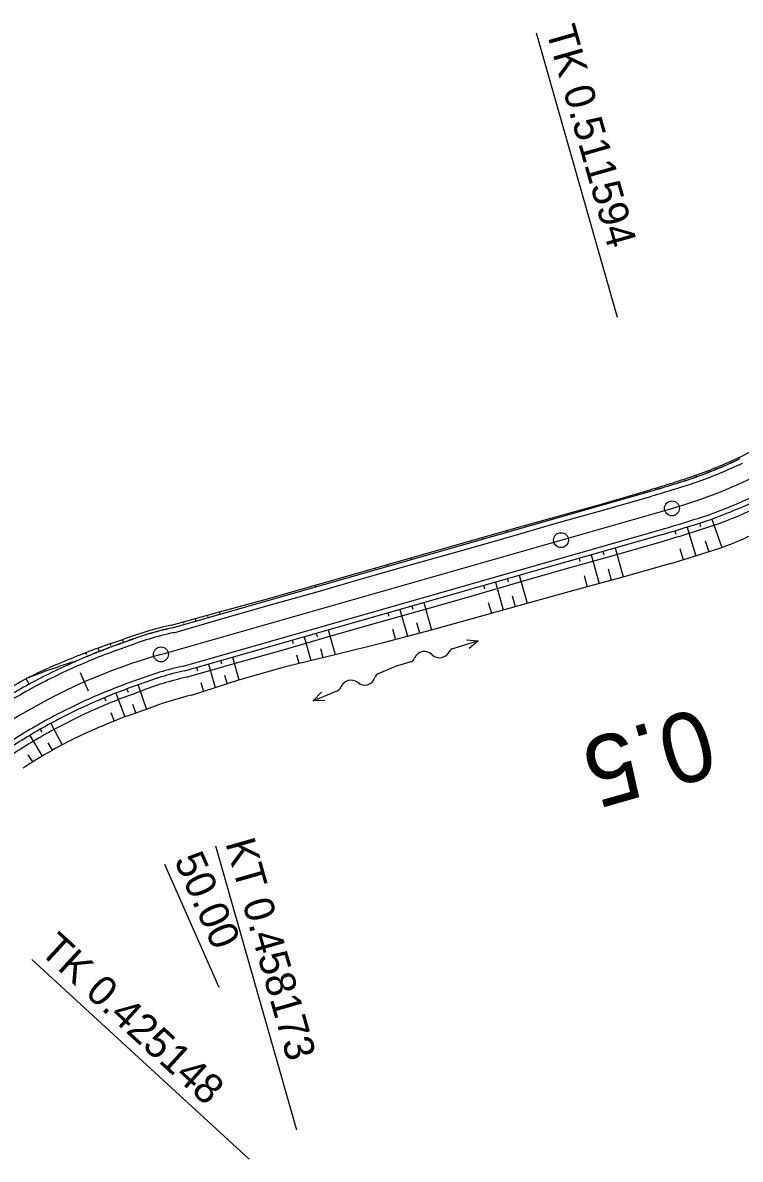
# Model space of a CAD drawing. Extents: x -481645 to -478728, y -1113199 to -1110710.
# Drawn here: x -479608.4 to -479536.3, y -1111488.4 to -1111374.2 of the extents above; entities that cross this region are included whole.
import ezdxf

# ---------------------------------------------------------------- set-up
doc = ezdxf.new("R2010")
doc.units = 0
for name, color, linetype in [('CP14_HATCH_SLOPE_L', 7, 'Continuous'), ('CP14_HECTOMETRY', 7, 'Continuous'), ('CP14_HLBODY', 7, 'Continuous'), ('CP1_HECTOMETRY', 7, 'Continuous'), ('O6_HATCH_SLOPE_L', 7, 'Continuous'), ('O6_HATCH_SLOPE_R', 7, 'Continuous'), ('O6_HECTOMETRY', 7, 'Continuous'), ('O6_HLBODY', 7, 'Continuous'), ('O6_HRANA_TELESO', 7, 'Continuous'), ('O6_OSA', 7, 'Continuous'), ('O6_VOZOVKA', 7, 'Continuous'), ('O6_ZPEVKRAJ', 7, 'Continuous')]:
    doc.layers.add(name, color=color, linetype=linetype)

# ---------------------------------------------------------------- blocks, each defined once
blk = doc.blocks.new('A$C70B')
at = {"layer": 'CP14_HLBODY'}
for p, q in [((0.87, 0), (-0.87, 0)), ((6.86, 0.43), (7.97, 0)), ((7.97, 0), (5.28, 0)), ((7.97, 0), (6.86, -0.48))]:
    blk.add_line(p, q, dxfattribs=at)
for centre, radius, start, end in [((0.87, 0.58), 0.582, 269.6924, 322.7901), ((2.17, -0.42), 1.05, 24.4039, 142.0836), ((4.08, 0.59), 1.11, 210.8873, 317.3707), ((5.32, -0.64), 0.636, 85.9766, 131.7248)]:
    blk.add_arc(centre, radius, start, end, dxfattribs=at)

msp = doc.modelspace()

# ---------------------------------------------------------------- linework, layer by layer
at = {"layer": 'CP14_HATCH_SLOPE_L'}
for p, q in [((-479539.17, -1111424.02), (-479538.14, -1111426.88)), ((-479542.88, -1111425.21), (-479542.79, -1111425.53)), ((-479541.64, -1111424.85), (-479540.76, -1111427.75)), ((-479540.4, -1111424.45), (-479540.29, -1111424.77)), ((-479539.82, -1111426.21), (-479539.44, -1111427.33)), ((-479551.3, -1111427.61), (-479550.48, -1111430.49)), ((-479550.1, -1111427.27), (-479550, -1111427.59)), ((-479548.89, -1111426.93), (-479548.07, -1111429.83)), ((-479542.38, -1111426.99), (-479542.05, -1111428.13)), ((-479552.5, -1111427.96), (-479552.41, -1111428.28)), ((-479559.71, -1111430.02), (-479559.62, -1111430.34)), ((-479558.51, -1111429.67), (-479557.71, -1111432.47)), ((-479552, -1111429.71), (-479551.68, -1111430.82)), ((-479549.59, -1111429.03), (-479549.27, -1111430.16)), ((-479562.11, -1111430.7), (-479562.02, -1111431.02)), ((-479560.91, -1111430.36), (-479560.12, -1111433.14)), ((-479568.12, -1111432.42), (-479567.35, -1111435.14)), ((-479561.63, -1111432.41), (-479561.32, -1111433.47)), ((-479559.22, -1111431.73), (-479558.92, -1111432.8)), ((-479571.73, -1111433.45), (-479571.64, -1111433.77)), ((-479570.53, -1111433.1), (-479569.76, -1111435.79)), ((-479569.33, -1111432.76), (-479569.23, -1111433.08)), ((-479568.85, -1111434.43), (-479568.55, -1111435.47)), ((-479580.14, -1111435.85), (-479579.47, -1111438.22)), ((-479578.94, -1111435.51), (-479578.85, -1111435.83)), ((-479577.74, -1111435.16), (-479577.04, -1111437.63)), ((-479571.26, -1111435.1), (-479570.97, -1111436.12)), ((-479581.35, -1111436.19), (-479581.25, -1111436.51)), ((-479587.36, -1111437.91), (-479586.71, -1111440.18)), ((-479580.92, -1111437.67), (-479580.68, -1111438.51)), ((-479578.51, -1111437.03), (-479578.25, -1111437.92)), ((-479590.96, -1111438.94), (-479590.87, -1111439.26)), ((-479589.76, -1111438.59), (-479589.09, -1111440.96)), ((-479588.56, -1111438.25), (-479588.47, -1111438.56)), ((-479588.14, -1111439.72), (-479587.9, -1111440.57)), ((-479599.09, -1111441.53), (-479598.16, -1111443.91)), ((-479597.97, -1111441.1), (-479597.85, -1111441.42)), ((-479596.83, -1111440.7), (-479595.99, -1111443.15)), ((-479590.53, -1111440.46), (-479590.28, -1111441.35)), ((-479600.21, -1111441.98), (-479600.08, -1111442.29)), ((-479597.41, -1111442.63), (-479597.08, -1111443.52)), ((-479599.59, -1111443.47), (-479599.24, -1111444.32)), ((-479605.63, -1111444.57), (-479604.48, -1111446.7)), ((-479607.72, -1111445.76), (-479606.48, -1111447.84)), ((-479606.69, -1111445.15), (-479606.52, -1111445.45)), ((-479605.91, -1111446.51), (-479605.48, -1111447.26)), ((-479607.93, -1111447.7), (-479607.47, -1111448.43))]:
    msp.add_line(p, q, dxfattribs=at)
at = {"layer": 'CP1_HECTOMETRY'}
msp.add_line((-479594.54, -1111437.62), (-479543.17, -1111422.95), dxfattribs=at)
for centre, radius, start, end in [((-479556.9, -1111374.87), 50, 285.9337, 309.1802), ((-479578.07, -1111495.31), 60, 105.9337, 137.4702)]:
    msp.add_arc(centre, radius, start, end, dxfattribs=at)
at = {"layer": 'O6_HATCH_SLOPE_L'}
msp.add_circle((-479554.32, -1111426.14), 0.75, dxfattribs=at)
at = {"layer": 'O6_HATCH_SLOPE_R'}
for p, q in [((-479540.69, -1111419.79), (-479540.76, -1111419.62)), ((-479542.96, -1111420.54), (-479543.01, -1111420.38)), ((-479541.85, -1111420.09), (-479541.88, -1111420.02)), ((-479541.82, -1111420.18), (-479541.82, -1111420.18)), ((-479552.53, -1111423.29), (-479552.57, -1111423.16)), ((-479551.35, -1111422.88), (-479551.36, -1111422.82)), ((-479551.33, -1111422.94), (-479551.33, -1111422.94)), ((-479550.13, -1111422.6), (-479550.16, -1111422.49)), ((-479553.76, -1111423.56), (-479553.77, -1111423.49)), ((-479553.73, -1111423.63), (-479553.74, -1111423.62)), ((-479560.97, -1111425.6), (-479561, -1111425.51)), ((-479559.74, -1111425.34), (-479559.79, -1111425.17)), ((-479563.38, -1111426.28), (-479563.4, -1111426.2)), ((-479563.35, -1111426.38), (-479563.35, -1111426.37)), ((-479562.15, -1111426.03), (-479562.2, -1111425.86)), ((-479560.95, -1111425.69), (-479560.95, -1111425.68)), ((-479572.99, -1111429.03), (-479573.01, -1111428.95)), ((-479571.76, -1111428.78), (-479571.81, -1111428.61)), ((-479570.59, -1111428.34), (-479570.61, -1111428.27)), ((-479570.56, -1111428.43), (-479570.56, -1111428.43)), ((-479569.36, -1111428.09), (-479569.41, -1111427.92)), ((-479572.97, -1111429.12), (-479572.97, -1111429.12)), ((-479580.2, -1111431.08), (-479580.23, -1111431)), ((-479580.18, -1111431.18), (-479580.18, -1111431.17)), ((-479578.98, -1111430.84), (-479579.03, -1111430.66)), ((-479588.59, -1111433.58), (-479588.66, -1111433.35)), ((-479592.24, -1111434.48), (-479592.27, -1111434.35)), ((-479592.2, -1111434.61), (-479592.2, -1111434.61)), ((-479590.99, -1111434.27), (-479591.07, -1111434.02)), ((-479589.83, -1111433.8), (-479589.86, -1111433.69)), ((-479589.79, -1111433.92), (-479589.79, -1111433.92)), ((-479600.73, -1111437.34), (-479600.86, -1111437)), ((-479599.58, -1111436.72), (-479599.63, -1111436.56)), ((-479599.52, -1111436.88), (-479599.52, -1111436.87)), ((-479598.3, -1111436.44), (-479598.39, -1111436.16)), ((-479602.01, -1111437.63), (-479602.09, -1111437.45)), ((-479601.93, -1111437.82), (-479601.94, -1111437.82)), ((-479607.78, -1111440.61), (-479608.09, -1111440.06))]:
    msp.add_line(p, q, dxfattribs=at)
at = {"layer": 'O6_HECTOMETRY'}
for p, q in [((-479556.81, -1111375.16), (-479548.66, -1111403.72)), ((-479589.05, -1111456.85), (-479580.9, -1111485.41)), ((-479607.54, -1111468.27), (-479585.66, -1111488.35))]:
    msp.add_line(p, q, dxfattribs=at)
for centre in [(-479543.17, -1111422.95), (-479594.54, -1111437.62), (-479594.54, -1111437.62)]:
    msp.add_circle(centre, 0.75, dxfattribs=at)
at = {"layer": 'O6_HLBODY'}
for p, q in [((-479601.82, -1111441.3), (-479602.62, -1111439.48)), ((-479601.82, -1111441.3), (-479602.62, -1111439.48)), ((-479594.17, -1111458.7), (-479588.73, -1111471.06))]:
    msp.add_line(p, q, dxfattribs=at)
at = {"layer": 'O6_HRANA_TELESO'}
for p, q in [((-479550.13, -1111422.59), (-479545.32, -1111421.22)), ((-479554.94, -1111423.96), (-479550.13, -1111422.59)), ((-479559.75, -1111425.34), (-479554.94, -1111423.96)), ((-479564.55, -1111426.71), (-479559.75, -1111425.34)), ((-479569.36, -1111428.08), (-479564.55, -1111426.71)), ((-479548.71, -1111427.57), (-479543.9, -1111426.2)), ((-479553.52, -1111428.94), (-479548.71, -1111427.57)), ((-479574.17, -1111429.45), (-479569.36, -1111428.08)), ((-479558.33, -1111430.31), (-479553.52, -1111428.94)), ((-479578.98, -1111430.83), (-479574.17, -1111429.45)), ((-479583.79, -1111432.2), (-479578.98, -1111430.83)), ((-479563.13, -1111431.69), (-479558.33, -1111430.31)), ((-479588.59, -1111433.57), (-479583.79, -1111432.2)), ((-479567.94, -1111433.06), (-479563.13, -1111431.69)), ((-479593.4, -1111434.94), (-479588.59, -1111433.57)), ((-479572.75, -1111434.43), (-479567.94, -1111433.06)), ((-479577.56, -1111435.8), (-479572.75, -1111434.43)), ((-479582.36, -1111437.18), (-479577.56, -1111435.8)), ((-479587.18, -1111438.53), (-479582.36, -1111437.18)), ((-479591.98, -1111439.92), (-479587.18, -1111438.53))]:
    msp.add_line(p, q, dxfattribs=at)
for centre, radius, start, end in [((-479556.9, -1111374.87), 47.74, 289.8361, 295.5657), ((-479585.46, -1111283.74), 143.22, 286.2737, 288.212), ((-479556.9, -1111374.87), 52.92, 289.8361, 295.5657), ((-479588.59, -1111273.86), 158.75, 286.3485, 288.2244), ((-479586.83, -1111465.37), 31.13, 102.1921, 111.6239), ((-479578.07, -1111495.31), 62.26, 108.9637, 113.7383), ((-479584.95, -1111498.19), 62.57, 106.893, 111.7018), ((-479585.96, -1111467.81), 28.53, 102.1841, 111.9235), ((-479577.99, -1111495.28), 57.06, 109.0427, 113.8173), ((-479578.07, -1111495.32), 57.06, 113.7302, 118.5049), ((-479578.08, -1111495.32), 57.06, 118.4928, 123.2674)]:
    msp.add_arc(centre, radius, start, end, dxfattribs=at)
at = {"layer": 'O6_OSA'}
for p, q in [((-479550.16, -1111422.49), (-479545.36, -1111421.08)), ((-479554.98, -1111423.83), (-479550.16, -1111422.49)), ((-479559.79, -1111425.17), (-479554.98, -1111423.83)), ((-479564.6, -1111426.55), (-479559.79, -1111425.17)), ((-479569.41, -1111427.92), (-479564.6, -1111426.55)), ((-479574.22, -1111429.29), (-479569.41, -1111427.92)), ((-479548.07, -1111429.83), (-479543.25, -1111428.47)), ((-479579.03, -1111430.66), (-479574.22, -1111429.29)), ((-479552.89, -1111431.15), (-479548.07, -1111429.83)), ((-479583.84, -1111432.03), (-479579.03, -1111430.66)), ((-479557.71, -1111432.47), (-479552.89, -1111431.15)), ((-479588.66, -1111433.35), (-479583.84, -1111432.03)), ((-479593.48, -1111434.69), (-479588.66, -1111433.35)), ((-479562.53, -1111433.8), (-479557.71, -1111432.47)), ((-479567.35, -1111435.14), (-479562.53, -1111433.8)), ((-479572.17, -1111436.44), (-479567.35, -1111435.14)), ((-479577.04, -1111437.63), (-479572.17, -1111436.44)), ((-479581.9, -1111438.81), (-479577.04, -1111437.63)), ((-479586.71, -1111440.18), (-479581.9, -1111438.81)), ((-479591.46, -1111441.73), (-479586.71, -1111440.18))]:
    msp.add_line(p, q, dxfattribs=at)
for centre, radius, start, end in [((-479557.01, -1111374.94), 47.59, 295.727, 301.4566), ((-479556.63, -1111374.76), 47.58, 289.4838, 295.2135), ((-479586.33, -1111284.4), 142.69, 286.6836, 288.6246), ((-479557.96, -1111375.33), 55.23, 291.0412, 296.7721), ((-479590.04, -1111269.36), 165.85, 286.3861, 288.2374), ((-479587.01, -1111465.29), 31.28, 101.9322, 111.3477), ((-479579.52, -1111495.86), 62.62, 107.5444, 112.3205), ((-479580.3, -1111496.35), 62.78, 111.4945, 116.2728), ((-479577.83, -1111495.17), 62.87, 118.7699, 123.5446), ((-479585.5, -1111468.66), 27.58, 102.4827, 112.3513), ((-479578.96, -1111495.65), 55.19, 107.9753, 112.7506), ((-479579.04, -1111495.78), 55.28, 112.6168, 117.3924), ((-479578.25, -1111495.43), 55.33, 118.2878, 123.0624)]:
    msp.add_arc(centre, radius, start, end, dxfattribs=at)
at = {"layer": 'O6_VOZOVKA'}
for p, q in [((-479549.99, -1111423.08), (-479545.18, -1111421.71)), ((-479554.8, -1111424.45), (-479549.99, -1111423.08)), ((-479559.61, -1111425.83), (-479554.8, -1111424.45)), ((-479549.03, -1111426.45), (-479544.22, -1111425.07)), ((-479564.42, -1111427.2), (-479559.61, -1111425.83)), ((-479553.84, -1111427.82), (-479549.03, -1111426.45)), ((-479569.22, -1111428.57), (-479564.42, -1111427.2)), ((-479558.65, -1111429.19), (-479553.84, -1111427.82)), ((-479574.03, -1111429.94), (-479569.22, -1111428.57)), ((-479578.84, -1111431.32), (-479574.03, -1111429.94)), ((-479563.45, -1111430.56), (-479558.65, -1111429.19)), ((-479568.26, -1111431.94), (-479563.45, -1111430.56)), ((-479583.65, -1111432.69), (-479578.84, -1111431.32)), ((-479573.07, -1111433.31), (-479568.26, -1111431.94)), ((-479588.45, -1111434.06), (-479583.65, -1111432.69)), ((-479577.88, -1111434.68), (-479573.07, -1111433.31)), ((-479593.26, -1111435.44), (-479588.45, -1111434.06)), ((-479582.69, -1111436.05), (-479577.88, -1111434.68)), ((-479587.49, -1111437.43), (-479582.69, -1111436.05)), ((-479592.3, -1111438.8), (-479587.49, -1111437.43))]:
    msp.add_line(p, q, dxfattribs=at)
for centre, radius, start, end in [((-479556.9, -1111374.87), 48.25, 289.8361, 295.5657), ((-479585.77, -1111282.76), 144.75, 286.2817, 288.2132), ((-479556.9, -1111374.87), 51.75, 289.8361, 295.5657), ((-479587.88, -1111276.09), 155.25, 286.3327, 288.2215), ((-479586.75, -1111465.62), 30.88, 102.1753, 111.635), ((-479578.07, -1111495.31), 61.75, 108.9637, 113.7383), ((-479578.07, -1111495.31), 61.75, 113.7383, 118.513), ((-479586.22, -1111467.28), 29.12, 102.0526, 111.7166), ((-479578.07, -1111495.31), 58.25, 108.9637, 113.7383), ((-479578.07, -1111495.31), 61.75, 118.513, 123.2876), ((-479578.07, -1111495.31), 58.25, 113.7383, 118.513), ((-479578.07, -1111495.31), 58.25, 118.513, 123.2876)]:
    msp.add_arc(centre, radius, start, end, dxfattribs=at)
at = {"layer": 'O6_ZPEVKRAJ'}
for p, q in [((-479550.13, -1111422.6), (-479545.32, -1111421.23)), ((-479554.94, -1111423.97), (-479550.13, -1111422.6)), ((-479559.74, -1111425.34), (-479554.94, -1111423.97)), ((-479564.55, -1111426.72), (-479559.74, -1111425.34)), ((-479548.89, -1111426.93), (-479544.09, -1111425.55)), ((-479569.36, -1111428.09), (-479564.55, -1111426.72)), ((-479553.7, -1111428.3), (-479548.89, -1111426.93)), ((-479574.17, -1111429.46), (-479569.36, -1111428.09)), ((-479558.51, -1111429.67), (-479553.7, -1111428.3)), ((-479578.98, -1111430.84), (-479574.17, -1111429.46)), ((-479563.32, -1111431.04), (-479558.51, -1111429.67)), ((-479583.78, -1111432.21), (-479578.98, -1111430.84)), ((-479568.12, -1111432.42), (-479563.32, -1111431.04)), ((-479588.59, -1111433.58), (-479583.78, -1111432.21)), ((-479572.93, -1111433.79), (-479568.12, -1111432.42)), ((-479593.4, -1111434.95), (-479588.59, -1111433.58)), ((-479577.74, -1111435.16), (-479572.93, -1111433.79)), ((-479582.55, -1111436.54), (-479577.74, -1111435.16)), ((-479587.36, -1111437.91), (-479582.55, -1111436.54)), ((-479592.16, -1111439.28), (-479587.36, -1111437.91))]:
    msp.add_line(p, q, dxfattribs=at)
for centre, radius, start, end in [((-479556.9, -1111374.87), 47.75, 289.8361, 295.5657), ((-479585.46, -1111283.72), 143.25, 286.2739, 288.212), ((-479556.9, -1111374.87), 52.25, 289.8361, 295.5657), ((-479588.18, -1111275.14), 156.75, 286.3395, 288.2228), ((-479586.83, -1111465.38), 31.12, 102.1917, 111.6241), ((-479578.07, -1111495.31), 62.25, 108.9637, 113.7383), ((-479578.07, -1111495.31), 62.25, 113.7383, 118.513), ((-479586.14, -1111467.52), 28.88, 102.0339, 111.7292), ((-479578.07, -1111495.31), 62.25, 118.513, 123.2876), ((-479578.07, -1111495.31), 57.75, 108.9637, 113.7383), ((-479578.07, -1111495.31), 57.75, 113.7383, 118.513), ((-479578.07, -1111495.31), 57.75, 118.513, 123.2876)]:
    msp.add_arc(centre, radius, start, end, dxfattribs=at)

# ---------------------------------------------------------------- block references
at = {"layer": 'CP14_HECTOMETRY'}
for p, rotation in [((-479570.25, -1111438.62), 17.32184632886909), ((-479571.88, -1111439.21), -157.3992275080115)]:
    msp.add_blockref('A$C70B', p, dxfattribs=dict(at, rotation=rotation))

# ---------------------------------------------------------------- texts
at = {"layer": 'O6_HATCH_SLOPE_L'}
msp.add_text('0.5', height=6.999, rotation=195.8881, dxfattribs=at).set_placement((-479540.12, -1111442.89))
at = {"layer": 'O6_HECTOMETRY'}
for s, rotation, p in [('TK 0.511594', 285.9337, (-479555.85, -1111374.89)), ('KT 0.458173', 285.9337, (-479588.09, -1111456.57)), ('TK 0.425148', 317.4702, (-479606.87, -1111467.54))]:
    msp.add_text(s, height=2.999, rotation=rotation, dxfattribs=at).set_placement(p)
at = {"layer": 'O6_HLBODY'}
msp.add_text('50.00', height=3, rotation=293.7383, dxfattribs=at).set_placement((-479593.25, -1111458.29))

doc.saveas('drawing.dxf')
